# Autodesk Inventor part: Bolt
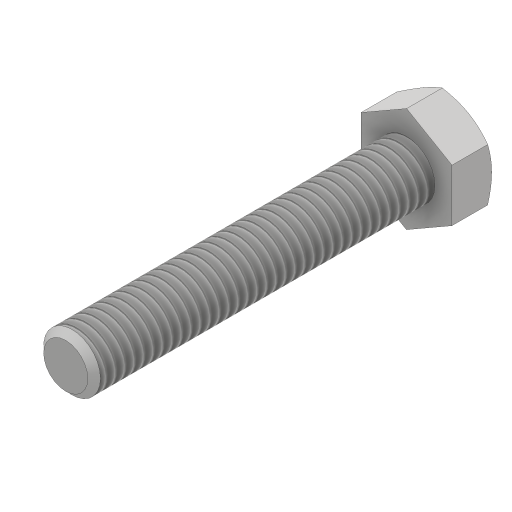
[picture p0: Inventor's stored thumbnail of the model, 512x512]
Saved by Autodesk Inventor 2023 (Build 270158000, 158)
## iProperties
Created: 2016-05
Part Number: Bolt
Material: Generic
Document SubType Name: Modeling
Designer: CADCIM
Density: 1 g/cm^3
Appearance: Default
Author: CADCIM
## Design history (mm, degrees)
sketch "Sketch1"
  geometry: L1 (3.604, -2.072)-(0.007, -4.157); L2 (0.007, -4.157)-(-3.596, -2.085); L3 (-3.596, -2.085)-(-3.604, 2.072); L4 (-3.604, 2.072)-(-0.007, 4.157); L5 (-0.007, 4.157)-(3.596, 2.085); L6 (3.596, 2.085)-(3.604, -2.072); 2 further points
  constraints: 12 end point, 1 coincident, 13 other
  dimensions: "d0" = 7.2 distance between parallel lines of L3 L6
extrude "Extrusion1" new body sketch "Sketch1" distance "d1" = 3.15; taper "d2" = 0 deg
sketch "Sketch2"
  geometry: C1 r 2.25 at (0, 0); 1 further point
  constraints: 1 centre point, 1 coincident
  dimensions: "d3" = 4.5 diameter of C1
extrude "Extrusion2" join sketch "Sketch2" distance "d4" = 27; taper "d5" = 0 deg
thread "Thread1" dims "d6" = 10, "d7" = 0
chamfer "Chamfer1" distance "d8" = 0.5; stored, may be unused: second distance "d9" = 2, angle "d10" = 45 deg
sketch "Sketch3"
  geometry: L1 (0.007, -4.157)-(3.604, -2.072) reference; C1 r 3.6 at (0, 0); 1 further point
  constraints: 1 centre point, 1 coincident, 1 tangent
extrude "Extrusion3" sketch "Sketch3" distance "d11" = 41; taper "d12" = 60 deg
body "Solid1"
